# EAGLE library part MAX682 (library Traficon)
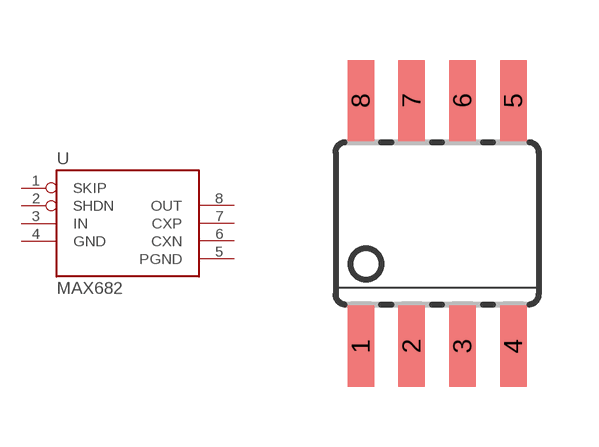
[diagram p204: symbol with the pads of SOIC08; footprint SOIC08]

Designator prefix U

## MAX682  [SOIC08]
1  SKIP  in
2  SHDN  in
3  IN  sup
4  GND  sup
5  PGND  sup
6  CXN
7  CXP
8  OUT  out

## Footprint SOIC08 (pad centres in mm)
Small Outline Package
smd 0.66 x 2.032: 1 -1.905,-3.073; 2 -0.635,-3.073; 3 0.635,-3.073; 4 1.905,-3.073; 5 1.905,3.073; 6 0.635,3.073; 7 -0.635,3.073; 8 -1.905,3.073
